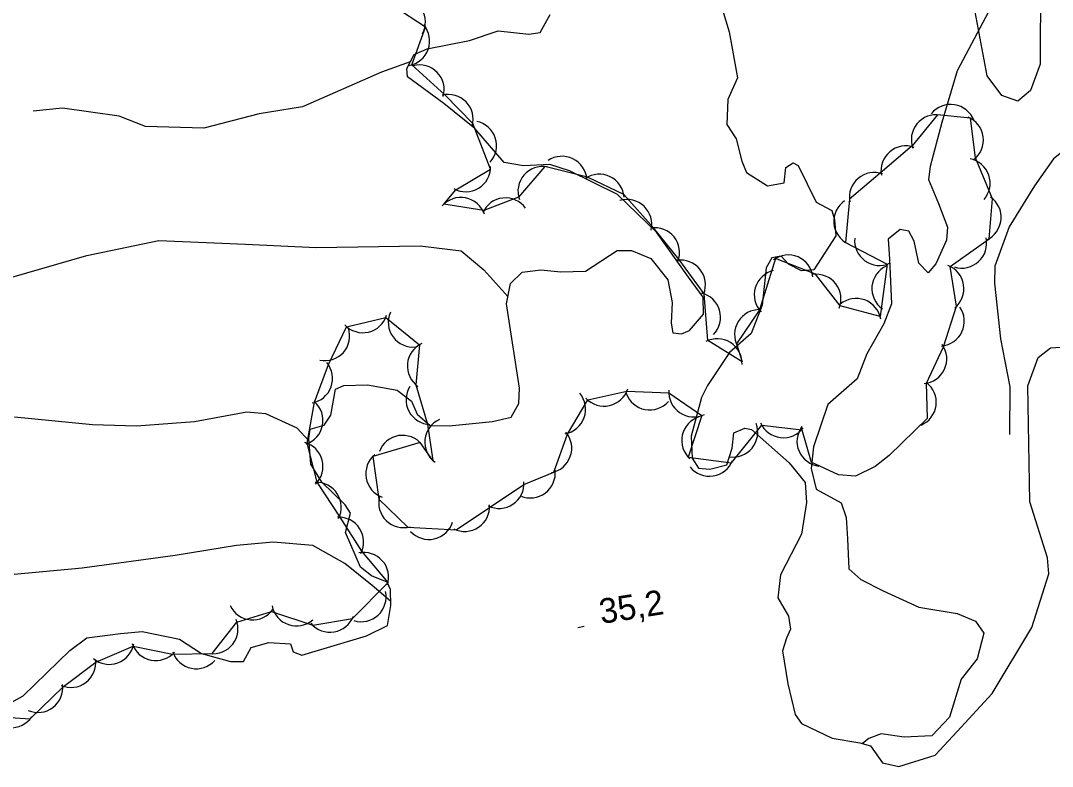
# Model space of a CAD drawing. Extents: x 646142 to 649934, y 5874075 to 5876351.
# Drawn here: x 647925.3 to 648049.9, y 5875650.1 to 5875740.3 of the extents above; entities that cross this region are included whole.
import ezdxf

# ---------------------------------------------------------------- set-up
doc = ezdxf.new("R2010")
doc.units = 0
for name, color, linetype in [('Niveau 1', 7, 'Continuous'), ('Niveau 2', 7, 'Continuous'), ('Niveau 22', 7, 'Continuous'), ('Niveau 3', 7, 'Continuous'), ('Niveau 44', 7, 'Continuous'), ('Niveau 54', 7, 'Continuous')]:
    doc.layers.add(name, color=color, linetype=linetype)

msp = doc.modelspace()

# ---------------------------------------------------------------- linework, layer by layer
at = {"layer": 'Niveau 1'}
msp.add_lwpolyline([(647970, 5875670.09), (647967.75, 5875671.98), (647964.46, 5875674.64), (647960.58, 5875676.79), (647955.8, 5875677.22), (647951.37, 5875676.82), (647943.97, 5875675.61), (647932.71, 5875674.05), (647924.53, 5875673.29)], dxfattribs=at)
at = {"layer": 'Niveau 2'}
for points in [[(648042.25, 5875741.34), (648038.43, 5875734.2), (648036.6, 5875727.96), (648035.17, 5875722.61), (648035, 5875721.05), (648036.19, 5875718.15), (648037.27, 5875715.3), (648037.16, 5875713.73), (648035.88, 5875710.87), (648034.93, 5875709.76), (648033.81, 5875710.94), (648033.26, 5875713.6), (648032.6, 5875714.82), (648031.55, 5875715.02), (648030.09, 5875713.82), (648030.27, 5875711.41), (648030.5, 5875706.02), (648029.6, 5875703.6), (648027.52, 5875699.98), (648026.37, 5875696.96), (648022.81, 5875693.86), (648021.07, 5875688.72), (648020.81, 5875686.11), (648021.4, 5875683.62), (648024.45, 5875681.96), (648025.05, 5875680.17), (648025.19, 5875677.59), (648025.35, 5875673.98), (648026.82, 5875672.71), (648029.51, 5875671.31), (648033.8, 5875669.35), (648038.45, 5875668.56), (648040.65, 5875667.64), (648041.67, 5875666.22), (648040.87, 5875663.11), (648038.93, 5875660.66), (648037.5, 5875656.06), (648035.38, 5875653.77), (648032.06, 5875653.62), (648029.27, 5875654.04), (648027.76, 5875653.46), (648026.99, 5875652.87)], [(647972.37, 5875735.28), (647968.91, 5875734.03), (647959.34, 5875729.84), (647954.12, 5875728.98), (647947.42, 5875727.25), (647940.39, 5875727.45), (647937.19, 5875728.7), (647930.34, 5875729.66), (647926.81, 5875729.31)], [(647916.55, 5875706.99), (647922.39, 5875708.71), (647933.29, 5875711.85), (647941.99, 5875713.67), (647952.46, 5875713.22), (647960.98, 5875712.85), (647973.58, 5875713.02), (647978.5, 5875712.43), (647981.26, 5875710.12), (647984.16, 5875706.91)], [(647924.54, 5875692.35), (647933.98, 5875691.44), (647939.28, 5875691.25), (647946.29, 5875691.8), (647952.61, 5875692.98), (647954.86, 5875692.75), (647958.66, 5875691.04), (647960.15, 5875689.4)]]:
    msp.add_lwpolyline(points, dxfattribs=at)
at = {"layer": 'Niveau 22'}
msp.add_lwpolyline([(648056.97, 5875728.14), (648052.68, 5875725.62), (648050.08, 5875723.57), (648047.8, 5875720.29), (648044.72, 5875715.33), (648043.01, 5875710.59), (648042.94, 5875708.51), (648043.68, 5875701.77), (648044.81, 5875695.98), (648044.78, 5875690.22)], dxfattribs=at)
at = {"layer": 'Niveau 3'}
msp.add_line((647992.6, 5875666.9), (647993.39, 5875667.03), dxfattribs=at)
at = {"layer": 'Niveau 44'}
for points in [[(648044.65, 5875753.35), (648046.84, 5875753.68), (648048.44, 5875752.58), (648049.11, 5875750.48), (648048.5, 5875745.01), (648048.48, 5875734.99), (648047.3, 5875731.8), (648045.78, 5875730.54), (648043.85, 5875731.22), (648042.08, 5875733.58), (648040, 5875744.61), (648040.18, 5875748.98), (648041.53, 5875751.76), (648044.65, 5875753.35)], [(648007.86, 5875707.22), (648004.8, 5875711.44), (648001.77, 5875715.22), (647998.17, 5875719.22), (647993.79, 5875721.33), (647988.61, 5875722.62), (647985.46, 5875718.93), (647981.27, 5875717.32), (647976.44, 5875718.08), (647977.89, 5875719.81), (647982.05, 5875722.31), (647979.92, 5875727.84), (647976.53, 5875731.31), (647972.54, 5875734.92), (647974.19, 5875739.49), (647970.4, 5875741.98)], [(648034.86, 5875692.21), (648034.76, 5875696.44), (648036.81, 5875700.83), (648038.38, 5875705.74), (648037.62, 5875710.53), (648042.3, 5875713.9), (648042.73, 5875718.73), (648040.68, 5875723.66), (648040.04, 5875728.47), (648036.08, 5875728.88), (648033.01, 5875725.12), (648029.14, 5875721.81), (648025.43, 5875718.68), (648024.97, 5875713.45), (648029.99, 5875710.81), (648029.14, 5875704.49), (648024.3, 5875705.77), (648021.31, 5875709.6), (648016.5, 5875711.51), (648014.55, 5875705.3), (648011.79, 5875701.17), (648012.45, 5875699), (648008.34, 5875701.58), (648007.86, 5875707.22)], [(647921.6, 5875656.16), (647926.44, 5875655.85), (647930.49, 5875659.76), (647934.36, 5875662.7), (647938.89, 5875664.65), (647943.65, 5875663.68), (647948.45, 5875663.73), (647951.43, 5875667.55), (647955.6, 5875668.84), (647960.58, 5875667.17), (647965.37, 5875667.98), (647969.69, 5875672.33), (647966.53, 5875676.13), (647963.9, 5875680.22), (647961.14, 5875684.46), (647959.92, 5875689.16), (647960.81, 5875694.12), (647962.47, 5875698.68), (647964.68, 5875703.26), (647969.4, 5875704.37), (647973.48, 5875701.06), (647973.05, 5875696.23), (647974.44, 5875691.46), (647975.11, 5875687.07), (647973.55, 5875689.25)], [(647973.55, 5875689.25), (647967.84, 5875687.56), (647968.59, 5875682.4), (647972.06, 5875679), (647977.92, 5875678.68), (647981.95, 5875681.38), (647986.11, 5875684.17), (647989.72, 5875685.68), (647991.35, 5875690.25), (647993.81, 5875694.4), (647998.54, 5875695.46), (648003.61, 5875695.26), (648007.61, 5875692.52), (648005.93, 5875687.49), (648011.18, 5875686.81), (648014.84, 5875691.36), (648019.66, 5875690.8), (648020.79, 5875686.87)], [(648034.86, 5875692.21), (648030.23, 5875687.68), (648028.53, 5875686.37), (648026.15, 5875685.18), (648024.11, 5875685.36), (648020.79, 5875686.87)]]:
    msp.add_lwpolyline(points, dxfattribs=at)
for centre, start, end in [((647971.2, 5875740.07), 331.7593, 91.7372), ((647971.71, 5875737.81), 280.0855, 40.0635), ((647973.47, 5875731.91), 344.4252, 104.4031), ((647976.97, 5875728.34), 344.4252, 104.4031), ((648037.66, 5875727.13), 21.1868, 141.1648), ((647979.79, 5875725.14), 318.3887, 78.3667), ((648035.91, 5875725.89), 80.8065, 200.7845), ((648038.61, 5875725.83), 307.5282, 67.5061), ((648032.24, 5875722.12), 70.1666, 190.1446), ((647990.71, 5875720.86), 4.2904, 124.2684), ((648039.43, 5875720.61), 319.0086, 78.9866), ((647979.07, 5875722.57), 241.0213, 0.9993), ((647988.38, 5875719.63), 79.4335, 199.4114), ((648028.42, 5875718.9), 70.1666, 190.1446), ((647995.21, 5875718.69), 4.2904, 124.2684), ((647978.48, 5875715.88), 18.9121, 138.8901), ((647983.88, 5875715.83), 36.144, 156.1219), ((647998.55, 5875715.64), 346.5349, 106.5128), ((648026.54, 5875716), 124.3492, 244.3272), ((648040.76, 5875716.47), 294.9022, 54.8801), ((648001.91, 5875712.23), 338.7021, 98.68), ((648029.06, 5875713.66), 174.1396, 294.1175), ((648039.01, 5875713.34), 252.6964, 12.6744), ((648018.04, 5875708.93), 6.9347, 126.9127), ((648005.03, 5875708.32), 338.7021, 98.68), ((648031.14, 5875707.87), 114.9025, 234.8805), ((648036.26, 5875707.86), 308.9771, 68.955), ((648016.93, 5875707.12), 103.4645, 223.4424), ((648021.41, 5875706.6), 338.0391, 98.0171), ((648006.85, 5875704.4), 316.3169, 76.2948), ((648026.25, 5875703.67), 9.8506, 129.8286), ((648036.31, 5875703.91), 274.9668, 34.9447), ((647966.64, 5875705.53), 223.2156, 343.1936), ((647972.71, 5875703.8), 156.3731, 276.3511), ((648014.56, 5875702.32), 88.5655, 208.5435), ((647962.05, 5875702.15), 258.161, 18.1389), ((648009.46, 5875698.8), 357.7998, 117.7777), ((647975.02, 5875698.49), 114.9025, 234.8805), ((648034.19, 5875699.38), 274.9668, 34.9447), ((647959.98, 5875697), 279.9473, 39.9252), ((647974.86, 5875694.43), 147.8575, 267.8354), ((647995.79, 5875696.65), 222.6082, 342.5861), ((648006.61, 5875695.34), 175.5527, 295.5307), ((648032.92, 5875694.12), 292.777, 52.7549), ((647990.56, 5875693.27), 280.3674, 40.3454), ((648001.3, 5875696.19), 199.1957, 319.1737), ((647958.82, 5875691.92), 288.5566, 48.5345), ((647977.12, 5875689.3), 114.0621, 234.04), ((648008.17, 5875689.49), 107.791, 227.769), ((648011.35, 5875690.49), 260.485, 20.463), ((648017.45, 5875692.83), 203.2986, 323.2766), ((648022.09, 5875689.39), 143.5022, 263.4801), ((647971.44, 5875687.12), 39.2417, 159.2197), ((647988.88, 5875688.56), 280.3674, 40.3454), ((647958.82, 5875686.37), 314.5314, 74.5094), ((647970, 5875685.48), 130.065, 250.0429), ((648008.51, 5875688.18), 218.881, 338.8589), ((647986.89, 5875685.55), 246.6774, 6.6553), ((647961.03, 5875681.43), 332.7505, 92.7284), ((647983.11, 5875684.28), 243.8269, 3.8048), ((647971.56, 5875681.96), 165.5769, 285.5548), ((647978.95, 5875681.5), 243.8269, 3.8048), ((647963.73, 5875677.22), 332.7505, 92.7284), ((647974.63, 5875680.53), 222.4284, 342.4063), ((647966.76, 5875672.96), 341.9554, 101.9333), ((647966.45, 5875670.58), 252.7448, 12.7228), ((647953.33, 5875670.81), 205.017, 324.995), ((647958.62, 5875670.08), 191.2606, 311.2385), ((647962.68, 5875669.31), 219.686, 339.6639), ((647948.55, 5875666.72), 262.0329, 22.0108), ((647936.01, 5875665.43), 229.9065, 349.8845), ((647941.62, 5875665.89), 198.5287, 318.5066), ((647946.52, 5875664.9), 198.5287, 318.5066), ((647931.36, 5875662.63), 247.1953, 7.1732), ((647927.38, 5875659.61), 247.1953, 7.1732), ((647924.13, 5875657.76), 206.3606, 326.3386)]:
    msp.add_arc(centre, 3, start, end, dxfattribs=at)
at = {"layer": 'Niveau 54'}
for points in [[(648009.68, 5875742.93), (648010.9, 5875738.89), (648011.9, 5875733.33), (648010.72, 5875730.71), (648010.6, 5875727.71), (648011.76, 5875725.96), (648012.43, 5875723.26), (648012.99, 5875721.92), (648015.52, 5875720.28), (648017.56, 5875720.67), (648017.76, 5875722.52), (648018.64, 5875723.05), (648019.24, 5875722.75), (648021.41, 5875718.32), (648023.32, 5875717.32), (648023.64, 5875716.2), (648023.78, 5875714.25), (648021.11, 5875710.13), (648019.62, 5875710.02), (648018.07, 5875710.82), (648017.19, 5875711.78), (648016.06, 5875711.58), (648015.35, 5875710.38), (648014.89, 5875705.86), (648013.54, 5875702.42), (648010.95, 5875700.14), (648008.27, 5875696.14), (648007.57, 5875694.71), (648006.32, 5875690.01), (648006.41, 5875687.37)], [(647990.57, 5875709.87), (647993.54, 5875709.98), (647997.36, 5875712.46), (647999.08, 5875712.48), (648001.45, 5875711.52), (648003.48, 5875708.92), (648004.03, 5875706.2), (648003.88, 5875703.67), (648004.08, 5875702.53), (648005.12, 5875702.38), (648006.12, 5875702.81), (648007.81, 5875704.78), (648007.76, 5875706.84), (648005.98, 5875709.23), (648002.12, 5875714.67), (647997.42, 5875719.24), (647991.59, 5875722.12), (647989.24, 5875722.85), (647986.04, 5875722.72), (647983.71, 5875723.12), (647980.19, 5875727.21), (647976.41, 5875730.24), (647972.03, 5875733.47), (647971.95, 5875734.49), (647972.86, 5875736.17), (647974.41, 5875736.87), (647979.51, 5875737.84), (647982.98, 5875739.03), (647986.69, 5875738.62), (647988.05, 5875738.84), (647989.27, 5875741.01)], [(647923.51, 5875657.44), (647925.59, 5875658.63), (647931.23, 5875664.11), (647933.29, 5875665.64), (647937.36, 5875666.18), (647939.97, 5875666.39), (647944.5, 5875665.48), (647947.14, 5875663.75), (647950.65, 5875662.76), (647952.24, 5875662.77), (647953.15, 5875664.45), (647955.27, 5875665.07), (647957.91, 5875664.93), (647958.21, 5875663.93), (647959.27, 5875663.55), (647967.09, 5875665.88), (647969.63, 5875667.11), (647970.01, 5875669.54), (647969.98, 5875671.48), (647969.57, 5875672.36), (647967.68, 5875673.13), (647966.35, 5875674.17), (647964.54, 5875678.38), (647965.16, 5875680.72), (647964.52, 5875681.7), (647961.67, 5875684.46), (647960.36, 5875686.65), (647960.13, 5875689.72), (647960.27, 5875690.88), (647961.95, 5875691.36), (647962.78, 5875692.57), (647963.34, 5875695.71), (647964.34, 5875696.13), (647967.2, 5875696.23), (647970.8, 5875695.6), (647972.5, 5875694.24), (647973.19, 5875692.69), (647974.79, 5875691.32), (647977.08, 5875691.27), (647982.31, 5875691.79), (647984.56, 5875692.31), (647985.47, 5875693.99), (647985.56, 5875695.83), (647983.98, 5875706.03), (647984.48, 5875708.48), (647985.87, 5875709.85), (647988.14, 5875710.14), (647990.57, 5875709.87)], [(648006.41, 5875687.37), (648007.19, 5875686.17), (648008.57, 5875686.04), (648010.6, 5875686.55), (648011.26, 5875688.55), (648011.46, 5875690.41), (648012.79, 5875690.97), (648013.61, 5875690.81), (648018.16, 5875686.79), (648020.07, 5875684.41), (648020.25, 5875682.01), (648019.62, 5875678.16), (648017.12, 5875673.25), (648016.76, 5875670.46), (648018.07, 5875668.26), (648018.31, 5875666.67), (648017.82, 5875665.6), (648017.36, 5875664.07), (648018, 5875660.09), (648018.86, 5875656.36), (648019.63, 5875655.27), (648023.33, 5875653.49), (648026.7, 5875652.95), (648027.99, 5875652.59), (648029.41, 5875650.51), (648031.39, 5875650.1), (648035.77, 5875651.47), (648038.43, 5875654.33), (648042.68, 5875658.92), (648047.47, 5875666.89), (648049.51, 5875673.38), (648049.36, 5875675.33), (648047.24, 5875682.07), (648046.99, 5875696.1), (648048.22, 5875699.53), (648049.74, 5875700.69), (648051.57, 5875700.83)]]:
    msp.add_lwpolyline(points, dxfattribs=at)

# ---------------------------------------------------------------- texts
at = {"layer": 'Niveau 3'}
msp.add_text('35,2 ', height=3, rotation=8.9405, dxfattribs=at).set_placement((647995.45, 5875667.31))

doc.saveas('drawing.dxf')
